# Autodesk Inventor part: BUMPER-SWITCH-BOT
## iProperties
Created: 2007-08
Part Number: BUMPER-SWITCH-BOT
Material: ABS Plastic
Document SubType Name: Modeling
Density: 1.06 g/cm^3
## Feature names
1. Base1
